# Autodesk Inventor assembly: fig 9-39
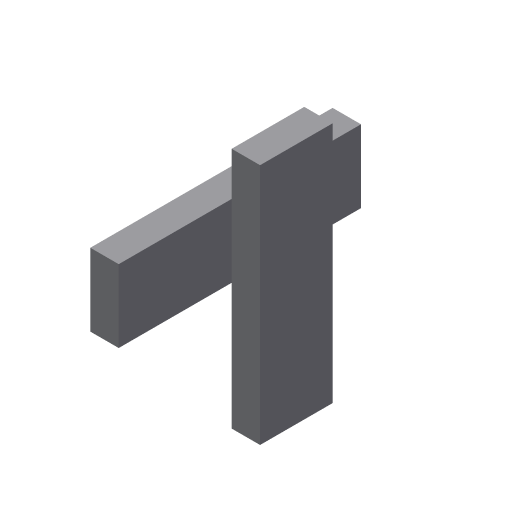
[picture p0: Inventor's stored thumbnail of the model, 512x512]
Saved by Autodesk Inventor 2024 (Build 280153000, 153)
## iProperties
Created: 2013-07
Part Number: fig 9-39
Document SubType Name: Assembly
Designer: CADCIM
Author: CADCIM
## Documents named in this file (2)
- D:\PROJECTS\Project 2023\RESOURCES INVENTOR 2024\RESOURCES INVENTOR 2024\Inventor_2023_Part\Inventor_2024_Part\c09_Inv_2024_prt\fig 9-40.iam
- D:\PROJECTS\Project 2023\RESOURCES INVENTOR 2024\RESOURCES INVENTOR 2024\Inventor_2023_Part\Inventor_2024_Part\c09_Inv_2024_prt\12.ipt
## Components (2 placed, 1 different names)
1. 12:1
2. 12:2
